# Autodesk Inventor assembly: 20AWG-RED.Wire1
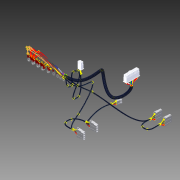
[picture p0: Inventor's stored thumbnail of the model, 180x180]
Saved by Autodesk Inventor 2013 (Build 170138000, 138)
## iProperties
Part Number: 20AWG-RED.Wire1
Material: Default
Description: 20AWG-RED
Density: 1 g/cm^3
Part Number: Wire Sleeve.Loom4
Description: Wire Sleeve
Stock Number: Wire Sleeve
Part Number: Wire Sleeve.Loom3
Part Number: Wire Sleeve.Loom1
Part Number: Wire Sleeve.Loom2
Part Number: 20AWG-YEL.Wire12
Description: 20AWG-YEL
Part Number: 20AWG-BLK.Wire4
Description: 20AWG-BLK
Part Number: 20AWG-RED.Wire2
Part Number: 20AWG-RED.Wire3
Part Number: 20AWG-BLK.Wire8
Part Number: 20AWG-BLK.Wire6
Part Number: 20AWG-BLK.Wire5
Part Number: 20AWG-BLK.Wire7
Part Number: 20AWG-YEL.Wire10
Part Number: 20AWG-BLK.Wire9
Part Number: 20AWG-YEL.Wire11
Part Number: 18AWG-GRY.Wire28
Description: 18AWG-GRY
Part Number: 20AWG-YEL.Wire20
Part Number: 20AWG-BLK.Wire16
Part Number: 20AWG-RED.Wire14
Part Number: 20AWG-RED.Wire13
Part Number: 20AWG-BLK.Wire15
Part Number: 20AWG-BLK.Wire18
Part Number: 20AWG-BLK.Wire17
Part Number: 20AWG-YEL.Wire19
Part Number: 18AWG-RED.Wire24
Description: 18AWG-RED
Part Number: 18AWG-ORG.Wire22
Description: 18AWG-ORG
Part Number: 18AWG-ORG.Wire21
Part Number: 18AWG-BLK.Wire23
Description: 18AWG-BLK
Stock Number: 18AWG-BLK
Part Number: 18AWG-RED.Wire26
Part Number: 18AWG-BLK.Wire25
Part Number: 18AWG-BLK.Wire27
Part Number: 18AWG-BLK.Wire36
Part Number: 18AWG-BLU.Wire32
Description: 18AWG-BLU
Part Number: 18AWG-YEL.Wire30
Description: 18AWG-YEL
Part Number: 18AWG-VIO.Wire29
Description: 18AWG-VIO
Part Number: 22AWG-ORG.Wire31
Description: 22AWG-ORG
Stock Number: 22AWG-ORG
Part Number: 18AWG-GRN.Wire34
Description: 18AWG-GRN
Stock Number: 18AWG-GRN
Part Number: 18AWG-BLK.Wire33
Part Number: 18AWG-BLK.Wire35
Part Number: 20AWG-YEL.Wire44
Part Number: 18AWG-RED.Wire40
Part Number: 18AWG-WHT.Wire38
Description: 18AWG-WHT
Stock Number: 18AWG-WHT
Part Number: 18AWG-BLK.Wire37
Part Number: 18AWG-RED.Wire39
Part Number: 20AWG-BLK.Wire42
Part Number: 20AWG-BLK.Wire41
Part Number: 20AWG-YEL.Wire43
ParentFileIdentifier: 5|1|0|0|178|2|0|0|80|0|65|0|84|0|72|0|83|0|59|0|67|0|58|0|92|0|80|0|114|0|111|0|103|0|114|0|97|0|109|0|32|0|70|0|105|0|108|0|101|0|115|0|92|0|65|0|117|0|116|0|1
Created: 2007-02
Part Number: Power Supply Harness
Document SubType Name: Assembly
Designer: floress
Mass: 16.0143 g
Surface Area: 329.274 cm^2
Volume: 16.0143 cm^3
HarnessSettings: <HarnessSettings><Defaults><Segments><Diameter value="0.200 in" fromwires="True"/><Offset value="0.100 in"/><ColorStyle value="Blue"/><BendRadius value="5" from
GlobalPropertyList: <PropertyList/>
CableDummyParamRefKey: Key:16|2|0|0|16|0|0|0|92|15|0|0|0|0|0|0|129|0|0|0|0|0|0|0|Level:1
Author: floress
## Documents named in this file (7)
- Z:\_DATEN\Personal Computer\Aip\Power Supply Harness.iam
- Z:\_DATEN\Personal Computer\Aip\Power Supply Harness.ipt
- Z:\_DATEN\Personal Computer\Aip\Floppy Drive Power Connector.ipt
- Z:\_DATEN\Personal Computer\Aip\Drive Power Connector.ipt
- Z:\_DATEN\Personal Computer\Aip\Power Supply Connector.ipt
- Z:\_DATEN\Personal Computer\Aip\Terminal Ring.ipt
- Z:\_DATEN\Personal Computer\Aip\Power Supply AUX Connector.ipt
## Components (91 placed, 57 different names)
1. Power Supply Connector:1
2. Power Supply AUX Connector:1
3. Drive Power Connector:1
4. Drive Power Connector:2
5. Floppy Drive Power Connector:1
6. Drive Power Connector:3
7. Drive Power Connector:4
8. Terminal Ring:1 — Mate:47, Mate:48, Mate:49, Mate:50, Mate:51, Mate:52
9. Terminal Ring:2 — Mate:50, Mate:51
10. Terminal Ring:3 — Mate:46, Mate:52
11. Terminal Ring:4
12. Terminal Ring:5
13. Terminal Ring:6
14. Terminal Ring:7
15. Terminal Ring:8
16. Terminal Ring:9 — Mate:68, Mate:69, Mate:70, Mate:71, Mate:78, Mate:79, Mate:80, Mate:81
17. Terminal Ring:10 — Mate:96, Mate:97, Mate:98, Mate:99
18. Terminal Ring:11 — Mate:45, Mate:46, Mate:47, Mate:48, Mate:49
19. Terminal Ring:12 — Mate:76, Mate:77, Mate:86, Mate:87, Mate:88, Mate:89
20. Terminal Ring:13 — Mate:72, Mate:73, Mate:74, Mate:75, Mate:82, Mate:83, Mate:84, Mate:85
21. Terminal Ring:14 — Mate:54, Mate:55, Mate:56, Mate:57
22. Terminal Ring:15 — Mate:54, Mate:55
23. Terminal Ring:16 — Mate:45
24. Terminal Ring:17 — Mate:96, Mate:97
25. Terminal Ring:18 — Mate:62, Mate:63, Mate:64, Mate:65
26. Terminal Ring:19 — Mate:66, Mate:67, Mate:68, Mate:69, Mate:78, Mate:79
27. Terminal Ring:20 — Mate:66, Mate:67
28. Terminal Ring:21 — Mate:76, Mate:77, Mate:86, Mate:87
29. Terminal Ring:22 — Mate:98, Mate:99
30. Terminal Ring:23 — Mate:94, Mate:95
31. Terminal Ring:24 — Mate:88, Mate:89, Mate:90, Mate:91
32. Terminal Ring:25 — Mate:92, Mate:93, Mate:94, Mate:95
33. Terminal Ring:26 — Mate:90, Mate:91, Mate:92, Mate:93
34. Terminal Ring:27 — Mate:59, Mate:60, Mate:61
35. Terminal Ring:28 — Mate:60, Mate:61, Mate:62, Mate:63
36. Terminal Ring:29 — Mate:56, Mate:57, Mate:59
37. Terminal Ring:30 — Mate:70, Mate:71, Mate:72, Mate:73, Mate:80, Mate:81, Mate:82, Mate:83
38. Terminal Ring:31 — Mate:74, Mate:75, Mate:84, Mate:85
39. Terminal Ring:32 — Mate:64, Mate:65
40. Power Supply Harness
41. HA_VC_368:1
42. HA_VC_369:1
43. HA_VC_370:1
44. HA_VC_371:1
45. HA_VC_372:1
46. HA_VC_373:1
47. HA_VC_374:1
48. HA_VC_421:1
49. HA_VC_424:1
50. HA_VC_427:1
51. HA_VC_430:1
52. HA_VC_433:1
53. HA_VC_436:1
54. HA_VC_439:1
55. HA_VC_442:1
56. HA_VC_445:1
57. HA_VC_448:1
58. HA_VC_451:1
59. HA_VC_454:1
60. HA_VC_457:1
61. HA_VC_460:1
62. HA_VC_463:1
63. HA_VC_466:1
64. HA_VC_469:1
65. HA_VC_472:1
66. HA_VC_475:1
67. HA_VC_478:1
68. HA_VC_481:1
69. HA_VC_484:1
70. HA_VC_487:1
71. HA_VC_490:1
72. HA_VC_493:1
73. HA_VC_496:1
74. HA_VC_499:1
75. HA_VC_502:1
76. HA_VC_505:1
77. HA_VC_508:1
78. HA_VC_511:1
79. HA_VC_514:1
80. HA_VC_517:1
81. HA_VC_520:1
82. HA_VC_523:1
83. HA_VC_526:1
84. HA_VC_529:1
85. HA_VC_532:1
86. HA_VC_535:1
87. HA_VC_538:1
88. HA_VC_541:1
89. HA_VC_544:1
90. HA_VC_547:1
91. HA_VC_550:1
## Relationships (53: Mate 53)
- Mate:45: Terminal Ring:11 ↔ Terminal Ring:16
- Mate:46: Terminal Ring:3 ↔ Terminal Ring:11
- Mate:47: Terminal Ring:1 ↔ Terminal Ring:11
- Mate:48: Terminal Ring:1 ↔ Terminal Ring:11
- Mate:49: Terminal Ring:1 ↔ Terminal Ring:11
- Mate:50: Terminal Ring:1 ↔ Terminal Ring:2
- Mate:51: Terminal Ring:1 ↔ Terminal Ring:2
- Mate:52: Terminal Ring:1 ↔ Terminal Ring:3
- Mate:54: Terminal Ring:14 ↔ Terminal Ring:15
- Mate:55: Terminal Ring:14 ↔ Terminal Ring:15
- Mate:56: Terminal Ring:14 ↔ Terminal Ring:29
- Mate:57: Terminal Ring:14 ↔ Terminal Ring:29
- Mate:59: Terminal Ring:27 ↔ Terminal Ring:29
- Mate:60: Terminal Ring:27 ↔ Terminal Ring:28
- Mate:61: Terminal Ring:27 ↔ Terminal Ring:28
- Mate:62: Terminal Ring:18 ↔ Terminal Ring:28
- Mate:63: Terminal Ring:18 ↔ Terminal Ring:28
- Mate:64: Terminal Ring:18 ↔ Terminal Ring:32
- Mate:65: Terminal Ring:18 ↔ Terminal Ring:32
- Mate:66: Terminal Ring:19 ↔ Terminal Ring:20
- Mate:67: Terminal Ring:19 ↔ Terminal Ring:20
- Mate:68: Terminal Ring:9 ↔ Terminal Ring:19
- Mate:69: Terminal Ring:9 ↔ Terminal Ring:19
- Mate:70: Terminal Ring:9 ↔ Terminal Ring:30
- Mate:71: Terminal Ring:9 ↔ Terminal Ring:30
- Mate:72: Terminal Ring:13 ↔ Terminal Ring:30
- Mate:73: Terminal Ring:13 ↔ Terminal Ring:30
- Mate:74: Terminal Ring:13 ↔ Terminal Ring:31
- Mate:75: Terminal Ring:13 ↔ Terminal Ring:31
- Mate:76: Terminal Ring:12 ↔ Terminal Ring:21
- Mate:77: Terminal Ring:12 ↔ Terminal Ring:21
- Mate:78: Terminal Ring:9 ↔ Terminal Ring:19
- Mate:79: Terminal Ring:9 ↔ Terminal Ring:19
- Mate:80: Terminal Ring:9 ↔ Terminal Ring:30
- Mate:81: Terminal Ring:9 ↔ Terminal Ring:30
- Mate:82: Terminal Ring:13 ↔ Terminal Ring:30
- Mate:83: Terminal Ring:13 ↔ Terminal Ring:30
- Mate:84: Terminal Ring:13 ↔ Terminal Ring:31
- Mate:85: Terminal Ring:13 ↔ Terminal Ring:31
- Mate:86: Terminal Ring:12 ↔ Terminal Ring:21
- Mate:87: Terminal Ring:12 ↔ Terminal Ring:21
- Mate:88: Terminal Ring:12 ↔ Terminal Ring:24
- Mate:89: Terminal Ring:12 ↔ Terminal Ring:24
- Mate:90: Terminal Ring:24 ↔ Terminal Ring:26
- Mate:91: Terminal Ring:24 ↔ Terminal Ring:26
- Mate:92: Terminal Ring:25 ↔ Terminal Ring:26
- Mate:93: Terminal Ring:25 ↔ Terminal Ring:26
- Mate:94: Terminal Ring:23 ↔ Terminal Ring:25
- Mate:95: Terminal Ring:23 ↔ Terminal Ring:25
- Mate:96: Terminal Ring:10 ↔ Terminal Ring:17
- Mate:97: Terminal Ring:10 ↔ Terminal Ring:17
- Mate:98: Terminal Ring:10 ↔ Terminal Ring:22
- Mate:99: Terminal Ring:10 ↔ Terminal Ring:22
## Named parameters: d128_d130 = 0, d129_d138 = 0, d133_d146 = 0, d134_d150 = 0, d135_d166 = 0, d158_d168 = 0, d159_d162 = 0
